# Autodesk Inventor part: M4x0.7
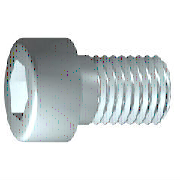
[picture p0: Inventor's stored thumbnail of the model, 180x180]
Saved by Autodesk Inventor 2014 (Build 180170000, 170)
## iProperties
IsCustomPart: 1
Created: 2015-10
Part Number: M4x0.7
Material: 강, 연강
Description: 6각머리 태핑 나사
Document SubType Name: Modeling
Standard: KS B 1003
Designer: mdu
Standards Organization: KS
Language: ko-KR
Size Designation: M 4 x 16
Categories: <MemberInstance><Categories><Category DisplayName="조임쇠" InternalName="e4da775c-781d-43d5-af7c-5136215cf5a6" Mnemonic="FSTN"><Category DisplayName="볼트" InternalN
Density: 7.86 g/cm^3
Appearance: 강철
Mass: 2.62973 g
Surface Area: 3.81118 cm^2
Volume: 0.334572 cm^3
Author: mdu
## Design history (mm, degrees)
sketch "스케치1"
  geometry: L1 (-1, 0)-(16, 0); L2 (16, 0)-(16, 2); L3 (16, 2)-(1.75, 2); L4 (1.75, 2)-(1.32, 2); L5 (1.32, 2)-(0, 2); L6 (0, 2)-(0, 3.5); L7 (0, 3.5)-(-4, 3.5); L8 (-4, 3.5)-(-4, 1.732); L9 (-4, 1.732)-(-2, 1.732); L10 (-2, 1.732)-(-1, 0); L11 (-8, 0)-(20, 0) reference; L12 (0, -0.7)-(0, 4.2) reference; L13 (1.75, 2)-(0, 2)
  constraints: 22 end point, 6 parallel, 2 collinear, 2 perpendicular, 1 horizontal, 1 point on line
  dimensions: "d1" = 14.25 distance from line of L3.end L2 (= GEL); "d2" = 0.42952 distance of L4.end L3.end (computed from GAL); "d3" = 4 distance between parallel lines of L8 L6 (= KOH); "d4" = 2 distance of L8.end L9.end (= INTI); "d5" = 60 deg angle of L10 L1; "d6" = 4 diameter of L3 L1 (= GD); "d7" = 4 diameter of L5 L1 (= BDM); "d8" = 3.4641 diameter of L9 L1 (= 1.1547 x SW); "d9" = 7 diameter of L7 L1 (= KOD); "d26" = 16 distance between parallel lines of L12 L2 (= NLG)
revolve "본체" sketch "스케치1" stored, may be unused: angle "d10" = 90 deg
sketch "스케치2"
  geometry: L1 (0, -4.9)-(0, 4.9) reference; L2 (-4.9, 0)-(4.9, 0) reference; L3 (1.732, 0)-(0.866, -1.5); L4 (0.866, -1.5)-(-0.866, -1.5); L5 (-0.866, -1.5)-(-1.732, 0); L6 (-1.732, 0)-(-0.866, 1.5); L7 (-0.866, 1.5)-(0.866, 1.5); L8 (0.866, 1.5)-(1.732, 0); 2 further points
  constraints: 12 end point, 1 coincident, 1 horizontal alignment, 1 point on line, 12 other
extrude "슬롯" join sketch "스케치2" stored distance "d11" = 10; taper "d12" = 0 deg
workplane "Work Plane1"
fillet "Fillet2" dims "d30" = 0.1 (= R)
body "Solid1"
fillet "모깎기1" dims "d17" = 0.4 (= RR)
feature "스레드" dims "d13" = 14.25 (= GEL), "d14" = 0
chamfer "모따기1" distance "d15" = 0.42941 (= -0.5 x SPD + 0.5 x GD); stored, may be unused: second distance "d16" = 0.42941 (= GUL), angle "d27" = 45 deg
other parameters: "GD" = 4 (= NND) [user parameter; used in 2 equation terms], "NLG" = 16 [user parameter; used in 1 equation term], "GEL" = 14.25 [user parameter; used in 2 equation terms], "KOD" = 7 [user parameter; used in 1 equation term], "KOH" = 4 [user parameter; used in 1 equation term], "INTI" = 2 [user parameter; used in 1 equation term], "GAL" = 0.42941 (= 0.61345 x PTC) [user parameter; used in 1 equation term], "GUL" = 0.42941 (= 0.61345 x PTC) [user parameter; used in 1 equation term], "BDM" = 4 (= NND) [user parameter; used in 1 equation term], "SW" = 3 [user parameter; used in 2 equation terms], "RR" = 0.4 [user parameter; used in 1 equation term], "SPD" = 3.14117 (= NND - 1.2269 x PTC) [user parameter; used in 1 equation term], "d19" = 0, "d28" = 0, "d29" = 0, "R" = 0.1 [user parameter; used in 1 equation term], "PHH" = 0.2 [user parameter], "GD1" = 3.14117 (= THREADDIA - 1.2269 x PTC) [user parameter], "THREADDIA" = 4 [user parameter; used in 1 equation term], "FAWI" = 45 deg [user parameter], "TPU" = 14.28571 (computed from PTC) [user parameter], "PTC" = 0.7 [user parameter; used in 5 equation terms], "NND" = 4 [user parameter; used in 3 equation terms], "TOA" = 30 deg [user parameter], "E0" = 3.465 (= 1.155 x SW) [user parameter]
